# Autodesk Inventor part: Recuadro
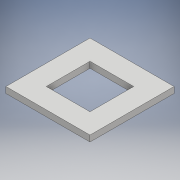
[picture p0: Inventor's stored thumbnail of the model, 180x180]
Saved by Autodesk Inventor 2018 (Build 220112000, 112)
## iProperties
Created: 2020-10
Part Number: Recuadro
Material: Genérico
Document SubType Name: Modeling
Designer: ULISES
Density: 1 g/cm^3
Appearance: Valor por defecto
Author: ULISES
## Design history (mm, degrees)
sketch "Boceto1"
  geometry: L1 (0, 0)-(50, 0); L2 (50, 0)-(50, 50); L3 (50, 50)-(0, 50); L4 (0, 50)-(0, 0); L5 (38, 12)-(12, 12); L6 (12, 12)-(12, 38); L7 (12, 38)-(38, 38); L8 (38, 38)-(38, 12)
  constraints: 16 end point, 4 parallel, 2 perpendicular, 1 horizontal, 3 other
  dimensions: "d0" = 50 distance of L3.end L1.start; "d1" = 50 distance of L1.start L1.end; "d2" = 12 distance between parallel lines of L1 L5
extrude "Extrusión1" new body sketch "Boceto1" distance "d3" = 3.6; taper "d4" = 0 deg
node "Sólido1"
